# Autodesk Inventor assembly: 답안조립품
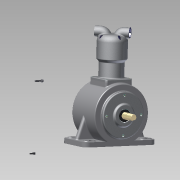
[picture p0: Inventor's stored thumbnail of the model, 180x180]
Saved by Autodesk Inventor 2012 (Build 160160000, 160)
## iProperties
Created: 2015-06
Part Number: 답안조립품
Document SubType Name: Assembly
Designer: User
Author: User
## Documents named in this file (15)
- C:\Documents and Settings\User\바탕 화면\450605V1015\답안조립품.iam
- C:\Documents and Settings\User\바탕 화면\450605V1015\본체.ipt
- C:\Documents and Settings\User\바탕 화면\450605V1015\메인 크랭크 축-구동부.ipt
- C:\Documents and Settings\User\바탕 화면\450605V1015\메인커버.ipt
- C:\Documents and Settings\User\바탕 화면\450605V1015\베어링 6204.ipt
- C:\Documents and Settings\User\바탕 화면\450605V1015\베어링 NA 4902.ipt
- C:\Documents and Settings\User\바탕 화면\450605V1015\실린더.ipt
- C:\Documents and Settings\User\바탕 화면\450605V1015\실린더헤드.ipt
- C:\Documents and Settings\User\바탕 화면\450605V1015\오일실.ipt
- C:\Documents and Settings\User\바탕 화면\450605V1015\커넥팅 로드.ipt
- C:\Documents and Settings\User\바탕 화면\450605V1015\크랭크 서브축.ipt
- C:\Documents and Settings\User\바탕 화면\450605V1015\피스톤.ipt
- C:\Documents and Settings\User\바탕 화면\450605V1015\피스톤 핀.ipt
- C:\Documents and Settings\User\바탕 화면\450605V1015\M4x0.7.ipt
- C:\Documents and Settings\User\바탕 화면\450605V1015\M5x0.8.ipt
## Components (4 placed, 4 different names)
1. 피스톤:1
2. 피스톤 핀:1
3. M4x0.7:1
4. M5x0.8:1
